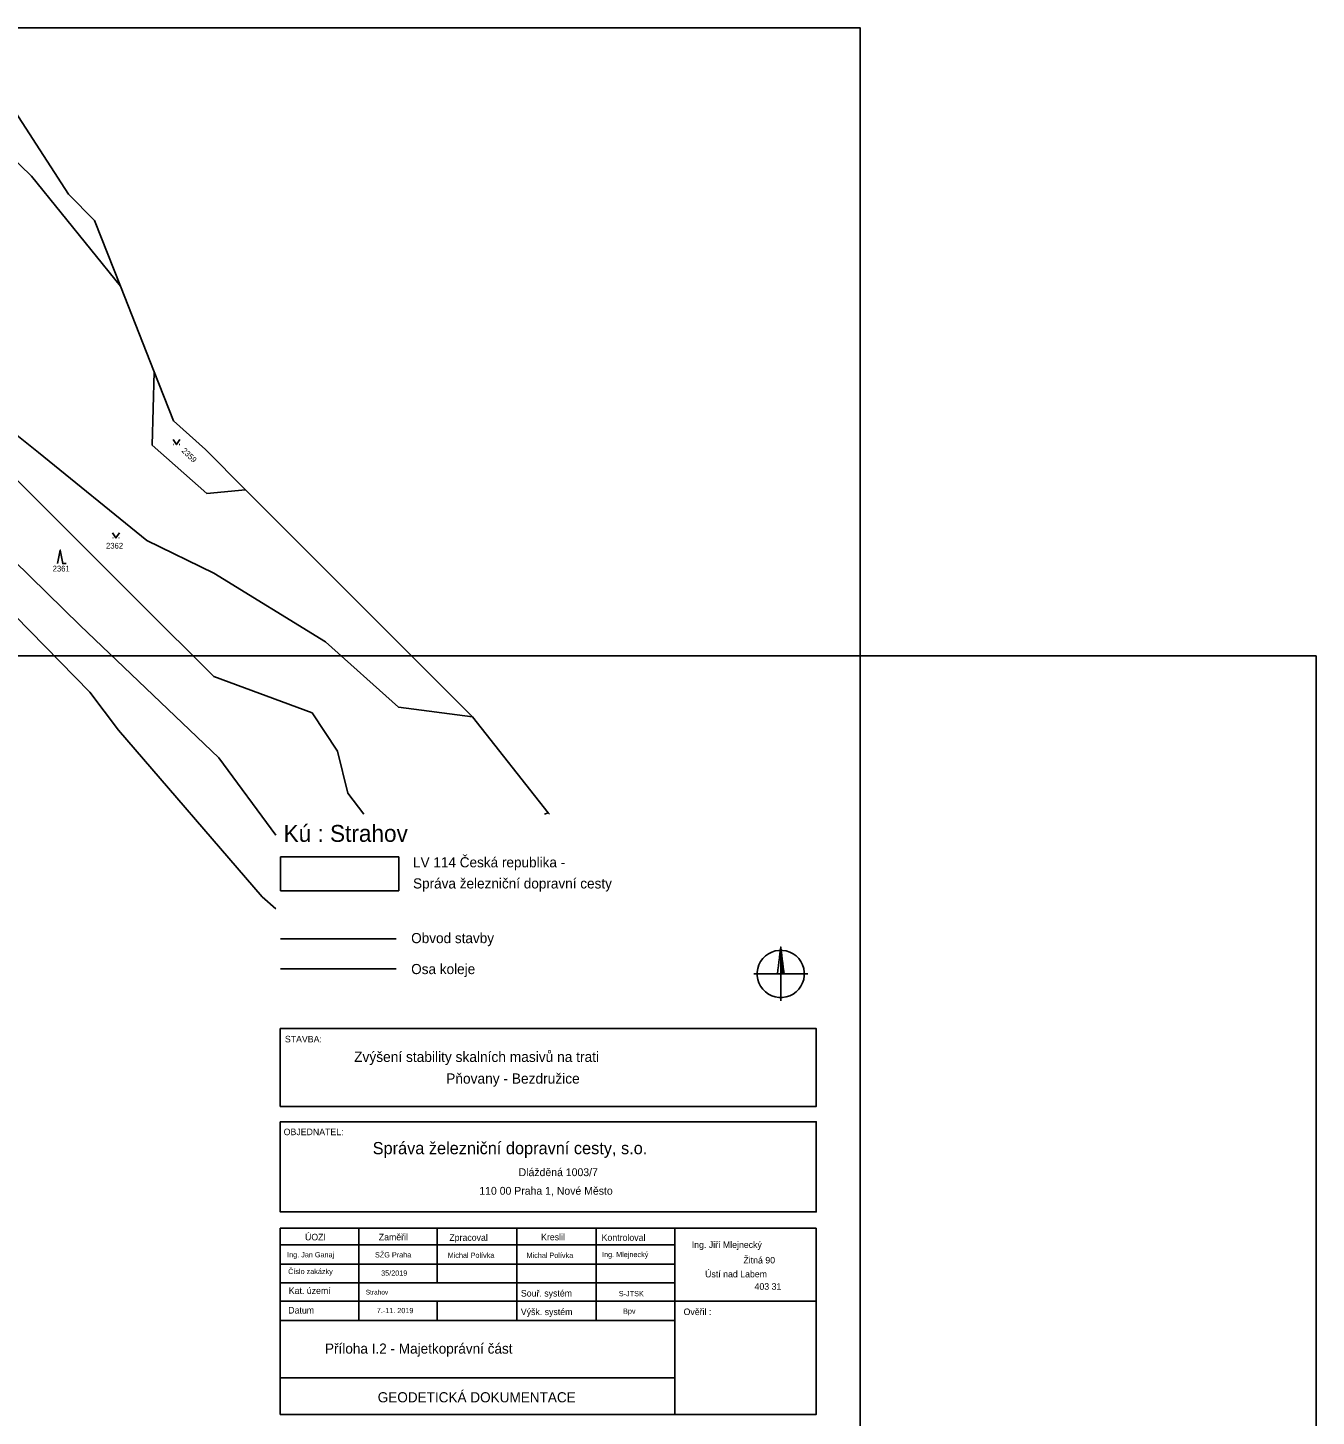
# Model space of a CAD drawing. Extents: x -852001 to -842497, y -1063614 to -1052182.
# Drawn here: x -849131.5 to -848750, y -1053225.1 to -1052814.2 of the extents above; entities that cross this region are included whole.
import ezdxf

# ---------------------------------------------------------------- set-up
doc = ezdxf.new("R2010")
doc.units = 0
for name, color, linetype in [('Default', 7, 'Continuous'), ('KLADY_ZMVM', 7, 'Continuous'), ('KN_HRANICE', 7, 'Continuous'), ('KN_KULTURY', 7, 'Continuous'), ('KN_PARCELY', 7, 'Continuous'), ('LEGENDA', 7, 'Continuous'), ('tabulka', 7, 'Continuous')]:
    doc.layers.add(name, color=color, linetype=linetype)

# ---------------------------------------------------------------- blocks, each defined once
blk = doc.blocks.new('SEVER')
at = {"layer": 'Default'}
for points in [[(5.5, 69.8), (16.3, 68.1), (26.7, 64.7), (36.5, 59.7), (45.4, 53.2), (53.2, 45.4), (59.7, 36.5), (64.7, 26.7), (68.1, 16.3), (69.8, 5.5), (69.8, -5.5), (68.1, -16.3), (64.7, -26.7), (59.7, -36.5), (53.2, -45.4), (45.4, -53.2), (36.5, -59.7), (26.7, -64.7), (16.3, -68.1), (5.5, -69.8), (-5.5, -69.8), (-16.3, -68.1), (-26.7, -64.7), (-36.5, -59.7), (-45.4, -53.2), (-53.2, -45.4), (-59.7, -36.5), (-64.7, -26.7), (-68.1, -16.3), (-69.8, -5.5), (-69.8, 5.5), (-68.1, 16.3), (-64.7, 26.7), (-59.7, 36.5), (-53.2, 45.4), (-45.4, 53.2), (-36.5, 59.7), (-26.7, 64.7), (-16.3, 68.1), (-5.5, 69.8), (5.5, 69.8)], [(-10, 0), (-8.5, 12), (-7, 24), (-5.5, 36), (-4, 48), (-2.5, 60), (-1, 72), (0, 80), (1.5, 68), (3, 56), (4.5, 44), (6, 32), (7.5, 20), (9, 8), (10, 0), (9.2, 0.8), (9.2, 5.6), (8.4, 12), (8.4, 0.8), (7.6, 0.8), (7.6, 13.5), (7.6, 18.4), (6.8, 24.8), (6.8, 12.1), (6.8, 0.8), (6, 0.8), (6, 13.5), (6, 26.2), (6, 31.2), (5.2, 36.8), (5.2, 24.1), (5.2, 11.4), (5.2, 0.8), (4.4, 0.8), (4.4, 13.5), (4.4, 26.2), (4.4, 38.9), (4.4, 43.2), (3.6, 50.4), (3.6, 37.7), (3.6, 25), (3.6, 12.3), (3.6, 0.8), (2.8, 0.8), (2.8, 13.5), (2.8, 26.2), (2.8, 38.9), (2.8, 51.6), (2.8, 56), (2, 63.2), (2, 50.5), (2, 37.8), (2, 25.1), (2, 12.4), (2, 0.8), (1.2, 0.8), (1.2, 13.5), (1.2, 26.2), (1.2, 38.9), (1.2, 51.6), (1.2, 64.3), (1.2, 69.6), (0.4, 76), (0.4, 63.3), (0.4, 50.6), (0.4, 37.9), (0.4, 25.2), (0.4, 12.5), (0.4, 0.8)], [(0, 80), (0, 67.3), (0, 54.6), (0, 41.9), (0, 29.2), (0, 16.5), (0, 3.8), (0, -8.9), (0, -21.6), (0, -34.3), (0, -47), (0, -59.7), (0, -72.4), (0, -80)], [(80, 0), (67.3, 0), (54.6, 0), (41.9, 0), (29.2, 0), (16.5, 0), (3.8, 0), (-8.9, 0), (-21.6, 0), (-34.3, 0), (-47, 0), (-59.7, 0), (-72.4, 0), (-80, 0)]]:
    blk.add_lwpolyline(points, dxfattribs=at)
blk = doc.blocks.new('308')
at = {"layer": 'Default'}
blk.add_lwpolyline([(-0.75, 0), (0, 4), (0.75, 0), (1.75, 0)], dxfattribs=at)
blk = doc.blocks.new('314')
at = {"layer": 'Default'}
for p, q in [((-0.95, 0), (-0.85, 0)), ((0.85, 0), (0.95, 0))]:
    blk.add_line(p, q, dxfattribs=at)
blk.add_lwpolyline([(-1, 1.5), (0, 0), (1, 1.5)], dxfattribs=at)

msp = doc.modelspace()

# ---------------------------------------------------------------- linework, layer by layer
at = {"layer": 'KLADY_ZMVM'}
for p in [(-849375, -1053000), (-848750, -1053500)]:
    msp.add_line(p, (-848750, -1053000), dxfattribs=at)
at = {"layer": 'KN_HRANICE'}
for p, q in [((-849159.24, -1052830.23), (-849130.37, -1052858.08)), ((-849119.37, -1052863.43), (-849140.56, -1052830.72)), ((-849130.37, -1052858.08), (-849104.04, -1052890.61)), ((-849111.68, -1052871.19), (-849119.37, -1052863.43)), ((-849104.04, -1052890.61), (-849111.68, -1052871.19)), ((-849094.05, -1052915.99), (-849104.04, -1052890.61)), ((-849164.08, -1052911.56), (-849128.24, -1052939.84)), ((-849094.05, -1052915.99), (-849094.67, -1052937.73)), ((-849088.33, -1052930.52), (-849094.05, -1052915.99)), ((-849078.85, -1052939.02), (-849088.33, -1052930.52)), ((-849094.67, -1052937.73), (-849078.47, -1052951.96)), ((-849066.96, -1052950.91), (-849078.85, -1052939.02)), ((-849128.24, -1052939.84), (-849096.23, -1052965.95)), ((-849135.85, -1052946.77), (-849097.92, -1052984.74)), ((-849078.47, -1052951.96), (-849066.96, -1052950.91)), ((-848999.77, -1053018.11), (-849066.96, -1052950.91)), ((-849147.7, -1052960.02), (-849115.97, -1052991.03)), ((-849096.23, -1052965.95), (-849076.36, -1052975.62)), ((-849076.36, -1052975.62), (-849043.32, -1052995.9)), ((-849139.7, -1052983.63), (-849113.12, -1053010.83)), ((-849097.92, -1052984.74), (-849076.36, -1053006.14)), ((-849074.9, -1053030.24), (-849115.97, -1052991.03)), ((-849043.32, -1052995.9), (-849021.72, -1053015.2)), ((-849076.36, -1053006.14), (-849047.3, -1053016.91)), ((-849113.12, -1053010.83), (-849104.61, -1053022.02)), ((-849047.3, -1053016.91), (-849039.79, -1053028.27)), ((-849021.72, -1053015.2), (-848999.77, -1053018.11)), ((-848977.37, -1053046.46), (-848999.77, -1053018.11)), ((-849104.61, -1053022.02), (-849062.09, -1053071.39)), ((-849039.79, -1053028.27), (-849036.74, -1053040.73)), ((-849074.9, -1053030.24), (-849058.01, -1053053.1)), ((-849036.74, -1053040.73), (-849031.95, -1053046.94)), ((-848978.47, -1053046.94), (-848977.37, -1053046.46)), ((-848977.37, -1053046.46), (-848977.03, -1053046.94)), ((-849062.09, -1053071.39), (-849058.01, -1053074.92))]:
    msp.add_line(p, q, dxfattribs=at)
at = {"layer": 'LEGENDA'}
for p, q in [((-849056.6, -1053059.54), (-849021.6, -1053059.54)), ((-849056.6, -1053059.54), (-849056.6, -1053069.54)), ((-849056.58, -1053083.82), (-849022.39, -1053083.82)), ((-849056.58, -1053092.65), (-849022.39, -1053092.65))]:
    msp.add_line(p, q, dxfattribs=at)
msp.add_lwpolyline([(-849479.05, -1053234.18), (-848885.05, -1053234.18), (-848885.05, -1052814.18), (-849479.05, -1052814.18)], close=True, dxfattribs=at)
msp.add_lwpolyline([(-849021.6, -1053059.54), (-849021.6, -1053069.54), (-849056.6, -1053069.54)], dxfattribs=at)
at = {"layer": 'tabulka'}
for p, q in [((-849056.68, -1053169.42), (-848898.02, -1053169.42)), ((-849033.39, -1053169.42), (-849033.39, -1053196.74)), ((-849010.24, -1053169.42), (-849010.24, -1053185.62)), ((-848986.64, -1053169.42), (-848986.64, -1053196.74)), ((-848963.19, -1053169.42), (-848963.19, -1053196.74)), ((-848939.89, -1053224.55), (-848939.89, -1053169.42)), ((-849056.68, -1053174.33), (-848939.89, -1053174.33)), ((-849056.68, -1053180.04), (-848939.89, -1053180.04)), ((-849056.68, -1053185.62), (-848939.89, -1053185.62)), ((-849056.68, -1053191.04), (-848898.02, -1053191.04)), ((-849010.24, -1053191.04), (-849010.24, -1053196.74)), ((-849056.68, -1053196.74), (-848939.89, -1053196.74)), ((-849056.68, -1053213.73), (-848939.89, -1053213.73))]:
    msp.add_line(p, q, dxfattribs=at)
for points in [[(-849056.68, -1053110.33), (-848898.02, -1053110.33), (-848898.02, -1053133.4), (-849056.68, -1053133.4)], [(-849056.68, -1053137.92), (-848898.02, -1053137.92), (-848898.02, -1053164.61), (-849056.68, -1053164.61)]]:
    msp.add_lwpolyline(points, close=True, dxfattribs=at)
msp.add_lwpolyline([(-848898.02, -1053169.42), (-848898.02, -1053224.55), (-849056.68, -1053224.55), (-849056.68, -1053169.42)], dxfattribs=at)

# ---------------------------------------------------------------- block references
at = {"layer": 'KN_KULTURY'}
for name, p in [('314', (-849087.43, -1052937.53)), ('314', (-849105.33, -1052965.16)), ('308', (-849121.85, -1052972.73))]:
    msp.add_blockref(name, p, dxfattribs=at)
at = {"layer": 'LEGENDA', "xscale": 0.1, "yscale": 0.10000000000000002}
msp.add_blockref('SEVER', (-848908.53, -1053094.18), dxfattribs=at)

# ---------------------------------------------------------------- texts
at = {"layer": 'KN_PARCELY'}
msp.add_text('2359', height=1.7, rotation=315.757, dxfattribs=at).set_placement((-849086.05, -1052939.52))
for s, p in [('2362', (-849108.28, -1052968.31)), ('2361', (-849124.08, -1052975.08))]:
    msp.add_text(s, height=1.7, dxfattribs=at).set_placement(p)
at = {"layer": 'LEGENDA'}
for s, height, p in [('Kú : Strahov', 5, (-849055.72, -1053055.09)), ('LV 114 Česká republika -', 3, (-849017.39, -1053062.64)), ('Správa železniční dopravní cesty', 3, (-849017.39, -1053068.89)), ('Obvod stavby', 3, (-849017.94, -1053085.07)), ('Osa koleje', 3, (-849017.94, -1053094.23)), ('Zvýšení stability skalních masivů na trati', 3.04, (-849034.84, -1053120.23)), ('Pňovany - Bezdružice', 3.04, (-849007.58, -1053126.65))]:
    msp.add_text(s, height=height, dxfattribs=at).set_placement(p)
at = {"layer": 'tabulka'}
for s, height, p in [('STAVBA:', 1.94, (-849055.33, -1053114.44)), ('OBJEDNATEL:', 1.94, (-849055.69, -1053141.9)), ('Správa železniční dopravní cesty, s.o.', 3.61, (-849029.34, -1053147.53)), ('Dlážděná 1003/7', 2.32, (-848986.13, -1053154.02)), ('110 00 Praha 1, Nové Město', 2.32, (-848997.77, -1053159.52)), ('ÚOZI', 1.94, (-849049.37, -1053173.02)), ('Zaměřil', 1.94, (-849027.54, -1053173.02)), ('Zpracoval', 1.94, (-849006.65, -1053173.17)), ('Kreslil', 1.94, (-848979.48, -1053173.02)), ('Kontroloval', 1.94, (-848961.57, -1053173.17)), ('Ing. Jiří Mlejnecký', 1.94, (-848934.88, -1053175.28)), ('Ing. Jan Ganaj', 1.552, (-849054.67, -1053178.05)), ('SŽG Praha', 1.552, (-849028.65, -1053178.08)), ('Michal Polívka', 1.552, (-849007.13, -1053178.2)), ('Michal Polívka', 1.552, (-848983.79, -1053178.24)), ('Ing. Mlejnecký', 1.552, (-848961.43, -1053177.98)), ('Žitná 90', 1.94, (-848919.59, -1053179.86)), ('Číslo zakázky', 1.552, (-849054.37, -1053183)), ('Ústí nad Labem', 1.94, (-848930.92, -1053183.98)), ('35/2019', 1.552, (-849026.84, -1053183.49)), ('403 31', 1.94, (-848916.29, -1053187.64)), ('Kat. území', 1.94, (-849054.18, -1053188.88)), ('Strahov', 1.397, (-849031.4, -1053189.05)), ('Souř. systém', 1.94, (-848985.46, -1053189.65)), ('S-JTSK', 1.552, (-848956.47, -1053189.56)), ('Datum', 1.94, (-849054.33, -1053194.68)), ('7.-11. 2019', 1.552, (-849028.12, -1053194.57)), ('Výšk. systém', 1.94, (-848985.48, -1053195.14)), ('Bpv', 1.552, (-848955.21, -1053194.75)), ('Ověřil :', 1.94, (-848937.3, -1053195.14)), ('Příloha I.2 - Majetkoprávní část', 3, (-849043.46, -1053206.55)), ('GEODETICKÁ DOKUMENTACE ', 3, (-849027.85, -1053220.96))]:
    msp.add_text(s, height=height, dxfattribs=at).set_placement(p)

doc.saveas('drawing.dxf')
